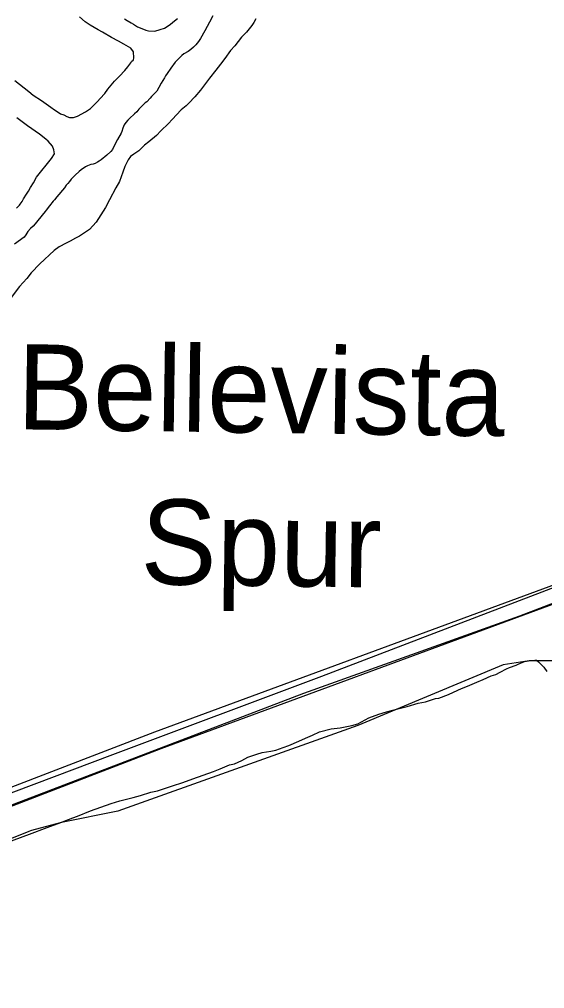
# Model space of a CAD drawing. Extents: x 3161564 to 3199464, y 849354 to 874788.
# Drawn here: x 3171907 to 3172800, y 858603 to 860252 of the extents above; entities that cross this region are included whole.
import ezdxf

# ---------------------------------------------------------------- set-up
doc = ezdxf.new("R2010")
doc.units = 0
for name, color, linetype in [('V-ROAD-CNTR', 7, 'Continuous'), ('V-SITE-VEGE', 7, 'Continuous'), ('V-TOPO-GNAM-IDEN', 7, 'Continuous'), ('V-TOPO-SHOR', 7, 'Continuous')]:
    doc.layers.add(name, color=color, linetype=linetype)

msp = doc.modelspace()

# ---------------------------------------------------------------- linework, layer by layer
at = {"layer": 'V-ROAD-CNTR'}
for points in [[(3173208.3, 859441.5), (3172807.5, 859286.6), (3172137, 859039.4), (3171457.7, 858777.7)], [(3173219.1, 859413.5), (3172818.1, 859258.5), (3172147.6, 859011.3), (3171468.4, 858749.7)]]:
    msp.add_lwpolyline(points, dxfattribs=at)
msp.add_spline([(3172633.8, 861383.8), (3172802.6, 860880.5), (3172972.2, 860440.5), (3173132.3, 860039.3), (3173355.9, 859565.2), (3173614.6, 859060.8), (3173833.8, 858663.3)], degree=3, dxfattribs=at)
at = {"layer": 'V-SITE-VEGE'}
for points in [[(3172309.1, 860253.2), (3172305.6, 860246.9), (3172302.1, 860242.1), (3172293.1, 860230.5), (3172284.7, 860221.9), (3172273.2, 860207.4), (3172266.2, 860199.2), (3172256.2, 860185.7), (3172249.2, 860176.1), (3172241.2, 860165.9), (3172230.3, 860152.4), (3172214.8, 860131.7), (3172205.3, 860120.6), (3172195.4, 860110.1), (3172190.4, 860105.3), (3172182, 860098.6), (3172166.6, 860082.2), (3172160.6, 860075.5), (3172147.7, 860063), (3172140.2, 860054.8), (3172127.4, 860044.3), (3172119.9, 860038.1), (3172110, 860028.5), (3172105.1, 860025.1), (3172101.6, 860023.2), (3172096.2, 860018.9), (3172092.2, 860013.6), (3172086.1, 860002), (3172083, 859992.3), (3172077.4, 859976.8), (3172070.9, 859965.6), (3172060.3, 859945.3), (3172053.2, 859932.3), (3172037.7, 859907.6), (3172026.2, 859895.1), (3172009.4, 859883.7), (3172002.5, 859879.9), (3171993.2, 859875.1), (3171986.3, 859871.8), (3171974.5, 859865.2), (3171966.1, 859859), (3171941.8, 859836.5), (3171926.8, 859821.1), (3171919.4, 859811.4), (3171907.4, 859798), (3171879.5, 859760.8)], [(3171899.1, 860148.2), (3171923.2, 860129.7), (3171930.4, 860123.3), (3171944.5, 860114.3), (3171948.8, 860111.3), (3171960.4, 860102.8), (3171966.7, 860098.7), (3171974.4, 860093.2), (3171976.8, 860091.7), (3171982.6, 860089.7), (3171987.9, 860087.2), (3171992.3, 860085.6), (3171999.1, 860085.5), (3172004.1, 860086.9), (3172006, 860087.8), (3172019.3, 860094.9), (3172027.7, 860100.7), (3172040.1, 860112.7), (3172044.6, 860117.5), (3172052.1, 860126.1), (3172057.6, 860133.8), (3172068.5, 860147.3), (3172077, 860155.5), (3172086.4, 860165.6), (3172091.4, 860171.4), (3172096.4, 860178.6), (3172097.9, 860180.5), (3172100.9, 860183.4), (3172101.4, 860186.8), (3172101.1, 860197.1), (3172096.3, 860203.5), (3172084.7, 860210.5), (3172075.5, 860215.1), (3172063.4, 860221.6), (3172048.5, 860230.7), (3172040.7, 860234.7), (3172027.2, 860242.3), (3172019, 860248.3), (3172009.3, 860256.7)], [(3172085.5, 860253.5), (3172090.3, 860250.5), (3172097.1, 860246.5), (3172100.9, 860244.5), (3172107.7, 860240), (3172112.5, 860237.9), (3172121.8, 860234.3), (3172126.6, 860232.8), (3172137.4, 860232.6), (3172146.7, 860235.4), (3172153.6, 860237.7), (3172163.4, 860243.9), (3172167.9, 860247.7), (3172175.8, 860253.9)], [(3171901.8, 859931.4), (3171907.3, 859936.2), (3171908.3, 859938.1), (3171911.8, 859942.4), (3171913.8, 859946.8), (3171918.8, 859955), (3171922.3, 859959.8), (3171925.9, 859966.1), (3171930.9, 859974.3), (3171935.9, 859984), (3171942.9, 859992.2), (3171954.9, 860007.1), (3171961.4, 860015.8), (3171966.9, 860023.5), (3171965.5, 860030.4), (3171963.2, 860036.8), (3171956, 860045.2), (3171952.1, 860048.7), (3171941.1, 860057.2), (3171920.8, 860071.2), (3171902.4, 860084.7)], [(3171871.5, 858846.8), (3171924.1, 858866), (3171954.5, 858877.2), (3171972.7, 858884.2), (3171997.8, 858893.6), (3172005.6, 858896.8), (3172028.2, 858905.7), (3172063.1, 858917.9), (3172077.8, 858922.5), (3172100.4, 858928.5), (3172113.2, 858931.7), (3172130.3, 858937.2), (3172142.1, 858939.5), (3172157.3, 858944.6), (3172167.2, 858948.3), (3172184.8, 858953.9), (3172202, 858960), (3172236.9, 858972.6), (3172248.7, 858977.3), (3172264.4, 858983.8), (3172272.8, 858985.6), (3172285.1, 858991.3), (3172295.4, 858997), (3172311.1, 859002.1), (3172320, 859004.9), (3172334.6, 859007.1), (3172343, 859008.9), (3172355.8, 859013.6), (3172365.1, 859016.8), (3172382.3, 859024.3), (3172393.6, 859029), (3172405.4, 859034.2), (3172417.2, 859039.9), (3172437.3, 859044.9), (3172452.5, 859046.6), (3172472.6, 859050.7), (3172482.9, 859053.9), (3172501.1, 859063.9), (3172518.3, 859069.9), (3172531.6, 859074.1), (3172553.2, 859079.6), (3172566.4, 859083.3), (3172585.1, 859088.8), (3172597.8, 859091.1), (3172615, 859096.6), (3172620.4, 859097.5), (3172636.6, 859103.6), (3172645.4, 859107.8), (3172659.2, 859113.5), (3172669, 859117.7), (3172685.3, 859124.3), (3172695.6, 859129), (3172709.4, 859135.1), (3172717.2, 859137.4), (3172724.6, 859141.7), (3172735.5, 859147.3), (3172740.9, 859149.7), (3172752.2, 859153.4), (3172755.6, 859155.3), (3172765.9, 859159.5), (3172772.8, 859160.9), (3172777.7, 859161.3), (3172784, 859162.2), (3172786.5, 859162.1), (3172789.9, 859159.1), (3172792.7, 859156.2), (3172799, 859150.2), (3172804.2, 859142.8)]]:
    msp.add_lwpolyline(points, dxfattribs=at)
at = {"layer": 'V-TOPO-SHOR'}
for points in [[(3172235.8, 860258.6), (3172230.3, 860247.8), (3172222.5, 860233), (3172214.9, 860219.6), (3172211.5, 860214.9), (3172206.9, 860209.2), (3172203.3, 860205), (3172198.5, 860201.1), (3172193.8, 860197.8), (3172186.8, 860193.5), (3172183.4, 860190.7), (3172172.1, 860179.5), (3172164.6, 860169.6), (3172158.6, 860160.5), (3172155.7, 860156.6), (3172153.8, 860153.1), (3172148.1, 860143.6), (3172144.2, 860136.3), (3172140.5, 860130.3), (3172137.6, 860126.8), (3172131.9, 860121.1), (3172129.4, 860118.3), (3172123.5, 860112.3), (3172120.8, 860110.2), (3172117, 860106.7), (3172112.7, 860102.3), (3172109.9, 860099.4), (3172106.5, 860095.2), (3172102.9, 860091.5), (3172094.1, 860083.6), (3172091.4, 860080.8), (3172088.2, 860076.8), (3172085.2, 860072.9), (3172083.1, 860067.1), (3172081.5, 860061.8), (3172079.9, 860058.7), (3172073.7, 860048.1), (3172068.4, 860037), (3172065.1, 860031.1), (3172062.4, 860027.6), (3172055.8, 860021.4), (3172045.9, 860013.4), (3172042.5, 860011.2), (3172039.8, 860009.2), (3172035.8, 860007.1), (3172032.6, 860006)], [(3172032.6, 860006), (3172028.6, 860005.2), (3172022.8, 860003), (3172019.2, 860001.3), (3172012.2, 859996.3), (3172008.8, 859993.7), (3172001.8, 859987.3), (3171995.2, 859980.5), (3171992, 859976.8), (3171989.1, 859972.9), (3171986.8, 859970.2), (3171983.6, 859966), (3171970.4, 859950.7), (3171966.6, 859945.6), (3171964.3, 859943.2), (3171958.1, 859935), (3171952.5, 859928), (3171950.6, 859925.4), (3171938.3, 859910.4), (3171936.3, 859907.3), (3171934, 859904.5), (3171930.4, 859900.7), (3171926.1, 859896.8), (3171921.5, 859891.5), (3171919.9, 859888.7), (3171917.7, 859886), (3171915.1, 859881.6), (3171898.9, 859870.1)], [(3173223.7, 859441.5), (3172420.8, 859134.2), (3172065.5, 859001), (3171797.3, 858899.7), (3171347.8, 858727.4)], [(3171394, 858720.3), (3171578.8, 858793.1), (3171898.5, 858917.5), (3172390.6, 859105.8), (3172758.3, 859237.2), (3173173.9, 859397.1), (3173216.6, 859407.8), (3173243.2, 859402.4), (3173262.8, 859395.3), (3173275.2, 859388.2), (3173278.7, 859384.7), (3173282.3, 859377.6)], [(3172827.5, 859160.9), (3172774.3, 859160.9), (3172729.8, 859153.8), (3172482.9, 859050.7), (3172074.4, 858905.1), (3171978.4, 858885.5), (3171925.1, 858871.3)], [(3171285.7, 858603.1), (3171342.5, 858627.9), (3171559.2, 858725.6), (3171925.1, 858871.3)]]:
    msp.add_lwpolyline(points, dxfattribs=at)

# ---------------------------------------------------------------- texts
at = {"layer": 'V-TOPO-GNAM-IDEN'}
for s, p in [('Bellevista', (3171902.2, 859554.9)), ('Spur', (3172112.4, 859291.4))]:
    msp.add_text(s, height=145, rotation=359.1825, dxfattribs=at).set_placement(p)

doc.saveas('drawing.dxf')
